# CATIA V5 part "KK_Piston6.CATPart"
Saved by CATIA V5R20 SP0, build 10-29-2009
Part number: Piston6
Bounding box of the stored display mesh (mm): x -90.915 to -58.307, y -18.689 to -0.937, z 33.904 to 105
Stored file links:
  G:\Khaled_CFAO_2011\ST2M\ST2M_GR1\msallin\Khaled\Version_Finale\KK_Piston6.CATPart
  C:\Users\Mathieu\Desktop\Think Motion\JOUG-MELEE2.CATProduct
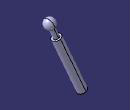
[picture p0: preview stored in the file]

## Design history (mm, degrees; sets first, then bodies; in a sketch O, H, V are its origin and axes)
External parameters (linked from other documents)
  `External.Taille du joug` = 100 mm
Set1
  Line1: linked copy from another document
  Line2: linked copy from another document
  Point1: linked copy from another document
Set2
  Plane1: type 2Lines, Element1 Line1, Element2 Line2
Body1 (main body)
  Sketch1 on Plane1, origin (-70.4493, -40.9938, 20.3771), H (-0.5029, 0.8643, 0), V (0.2096, 0.122, 0.9701)
    point P1 (39.3742, 15.5054)
    line L1 (39.3742, 15.5054) -> (43.3748, 16.6697)
    line L2 (43.3748, 16.6697) -> (28.0052, 69.4786)
    line L3 (28.0052, 69.4786) -> (26.4049, 69.0128)
    line L4 (26.4049, 69.0128) -> (23.6104, 78.6144)
    arc A1 centre (20, 82.0734) radius 5 from (23.6104, 78.6144) to (18.6028, 86.8742) ccw
    point P6 (20, 82.0734)
    point P7 (18.6028, 86.8742)
    reference projected line E1 (20, 82.0734) -> (50, -21.0042) from Line1
    reference projected line E2 (20, 82.0734) -> (50, -21.0042) from Line1
    reference projected line E3 (20, 82.0734) -> (50, -21.0042) from Line1
    reference projected point E4 (20, 82.0734) from Point1
    reference projected line E5 (20, 82.0734) -> (50, -21.0042) from Line1
    distance P1 E1 = 0
    length L2 = 55 {= `External.Taille du joug` *(7/10-1/10-1/20)}
    length L4 = 10 {= `External.Taille du joug` /10}
    distance L2 E2 = 4.1667 {= `External.Taille du joug` /24}
    distance L4 E3 = 2.5 {= `External.Taille du joug` /40}
    distance P6 E4 = 0
    distance P7 E5 = 0
    radius A1 = 5 {= `External.Taille du joug` /20}
    perpendicularity: L2 L1
    parallelism: L3 L1, L4 L2
  Shaft1: profile Sketch1, axis Line1, angle 360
